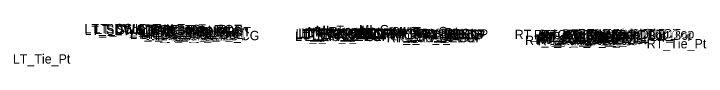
# Model space of a CAD drawing. Extents: x -26 to 4229, y -10 to 9523.
# Drawn here: x 1068.1 to 1216.7, y 12.5 to 21.6 of the extents above; entities that cross this region are included whole.
import ezdxf

# ---------------------------------------------------------------- set-up
doc = ezdxf.new("R2010")
doc.units = 0
doc.layers.add('Default', color=7, linetype='Continuous')

msp = doc.modelspace()

# ---------------------------------------------------------------- texts
at = {"layer": 'Default'}
for s, p in [('LT_SDWK_Out_Top', (1083.24, 19.57)), ('LT_SDWK_Out_Bot', (1083.27, 19.23)), ('LT_CSLP_Pnt', (1085.17, 19.59)), ('LT_Sub_Trench_Out_DLT', (1085.53, 19.39)), ('LT_SDWK_In_Top', (1089.86, 19.47)), ('LT_SDWK_In_Bot', (1089.89, 19.13)), ('LT_CG_Top_Face', (1094.76, 19.35)), ('LT_CG_Top_BOC', (1095.28, 19.35)), ('LT_CG_Top_Gut', (1095.74, 18.85)), ('LT_PV1_OEOT', (1100.24, 18.92)), ('MI_Face In', (1131.15, 18.93)), ('MI_Top In', (1132.86, 19.18)), ('MI_Crown', (1142.17, 19.36)), ('MI_Top Out', (1149.42, 18.95)), ('LT_CG1_Shelf_Out', (1093.05, 18.36)), ('LT_CG_Bot_BOC', (1095.31, 18.35)), ('LT_Sub_OEOP', (1096.36, 18.11)), ('LT_Sub_OEOT_CG', (1096.87, 18.09)), ('LT_CG_Bot_IE', (1099.41, 18.34)), ('LT_Sub_OEOT', (1099.58, 18.05)), ('LT_PV2_OEOT', (1099.67, 18.67)), ('LT_PV3_OEOT', (1099.67, 18.42)), ('LT_Sub_OEEOP', (1128.46, 17.89)), ('LT_PV2_OEEOP', (1128.56, 18.51)), ('LT_PV3_OEEOP', (1128.56, 18.26)), ('LT_PV1_OEEOP', (1129.12, 18.64)), ('LT_PV2_IEEOP', (1129.2, 18.51)), ('LT_PV1_IEEOP', (1129.77, 18.64)), ('LT_PV2_PGL1', (1130.13, 18.51)), ('LT_PV3_PGL1', (1130.13, 18.26)), ('LT_PV2_PGL', (1130.46, 18.51)), ('LT_PV4_PGL', (1130.46, 17.89)), ('LT_PV1_PGL', (1131.03, 18.76)), ('MI_Bot In', (1132.13, 18.76)), ('RT_Sub_OEEOP', (1148.12, 17.65)), ('RT_PV2_OEEOP', (1148.21, 18.28)), ('RT_PV3_OEEOP', (1148.21, 18.03)), ('RT_PV1_OEEOP', (1148.78, 18.4)), ('RT_PV2_IEEOP', (1148.86, 18.28)), ('MI_Face Out', (1149.21, 18.7)), ('RT_PV1_IEEOP', (1149.42, 18.4)), ('RT_PV2_PGL1', (1149.79, 18.28)), ('RT_PV3_PGL1', (1149.79, 18.03)), ('RT_PV2_PGL', (1150.12, 18.28)), ('RT_PV4_PGL', (1150.12, 17.65)), ('MI_Bot Out', (1150.21, 18.53)), ('RT_PV1_PGL', (1150.68, 18.53)), ('RT_Sub_Trench_Out_DLT', (1175.59, 18.32)), ('RT_CG_Top_Face', (1179.71, 18.28)), ('RT_CG1_Shelf_Out', (1180, 17.25)), ('RT_CG_Bot_IE', (1180.37, 17.31)), ('RT_PV2_OEOT', (1180.63, 17.65)), ('RT_PV3_OEOT', (1180.63, 17.4)), ('RT_CG_Top_Gut', (1180.69, 17.78)), ('RT_PV1_OEOT', (1181.19, 17.9)), ('RT_CG_Top_BOC', (1181.24, 18.28)), ('RT_SDWK_In_Top', (1185.81, 18.39)), ('RT_SDWK_In_Bot', (1185.84, 18.06)), ('RT_SDWK_Out_Top', (1189.19, 18.49)), ('RT_SDWK_Out_Bot', (1189.22, 18.16)), ('RT_Shld_O', (1195.54, 18.48)), ('CSLP_Pnt', (1197.87, 18.52)), ('RT_Sub_OEOT_CG', (1177.82, 17.06)), ('RT_Sub_OEOT', (1180.53, 17.02)), ('RT_CG_Bot_BOC', (1181.27, 17.26)), ('RT_Sub_OEOP', (1183.82, 17)), ('RT_Tie_Pt', (1203.94, 16.34)), ('LT_Tie_Pt', (1067.87, 13.07))]:
    msp.add_text(s, height=2, dxfattribs=at).set_placement(p)

doc.saveas('drawing.dxf')
